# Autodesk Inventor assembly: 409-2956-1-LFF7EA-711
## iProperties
Created: 2010-06
Part Number: 409-2956-1-LFF7EA-711
Document SubType Name: Weldment
Designer: S. Boerckel
Mass: 16743.3 g
Surface Area: 4754.08 cm^2
Volume: 2131.13 cm^3
Density: 7.85654 g/cm^3
Description: PUMP INLET
Weld Material: Welded Steel Mild
Material: WELDMENT
Author: S. Boerckel
Revision Number: A
Subject: DEMIN WATER FORWARDING PUMP SKID-7EA
